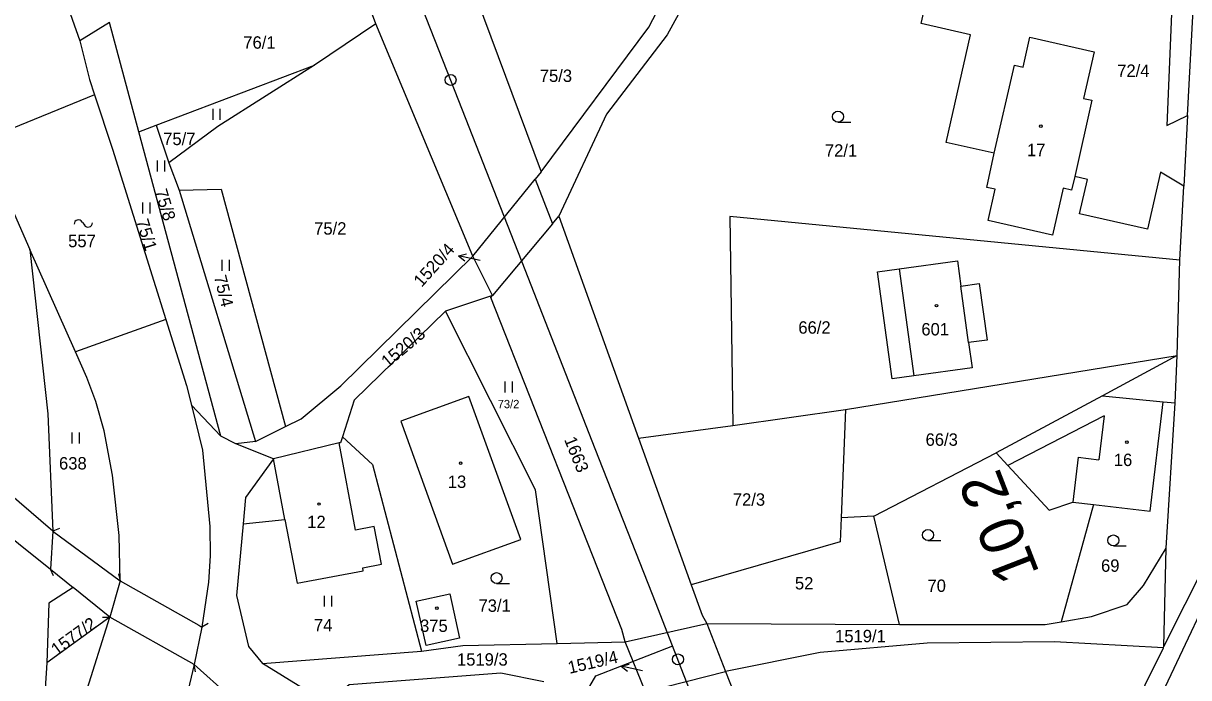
# Model space of a CAD drawing. Extents: x -553916 to -552953, y -1067470 to -1066637.
# Drawn here: x -553633.4 to -553473.7, y -1066907.8 to -1066818.1 of the extents above; entities that cross this region are included whole.
import ezdxf

# ---------------------------------------------------------------- set-up
doc = ezdxf.new("R2010")
doc.units = 0
for name, color, linetype in [('Hranice parcel', 7, 'Continuous'), ('Kolej', 7, 'Continuous'), ('Návěst místo trati', 7, 'Continuous'), ('Parcelní čísla', 7, 'Continuous'), ('Pop  PČ popisy', 7, 'Continuous'), ('Přejezd - štěrkové lože', 7, 'Continuous'), ('Vnitřní kresba', 7, 'Continuous'), ('Vrstva 1', 7, 'Continuous'), ('Značky budov', 7, 'Continuous'), ('Značky kultur', 7, 'Continuous')]:
    doc.layers.add(name, color=color, linetype=linetype)

msp = doc.modelspace()

# ---------------------------------------------------------------- linework, layer by layer
at = {"layer": 'Hranice parcel'}
for p, q in [((-553473.84, -1066830.72), (-553472.63, -1066808.29)), ((-553621.6, -1066817.99), (-553625.66, -1066820.5)), ((-553617.57, -1066832.95), (-553621.6, -1066817.99)), ((-553585.12, -1066818.17), (-553593.5, -1066823.84)), ((-553615.21, -1066832.06), (-553593.5, -1066823.84)), ((-553623.67, -1066827.87), (-553637.71, -1066833.62)), ((-553476.7, -1066832.08), (-553473.84, -1066830.72)), ((-553473.84, -1066830.72), (-553474.36, -1066840.41)), ((-553617.57, -1066832.95), (-553615.21, -1066832.06)), ((-553615.21, -1066832.06), (-553613.46, -1066837.22)), ((-553606.33, -1066874.71), (-553617.57, -1066832.95)), ((-553613.46, -1066837.22), (-553612.07, -1066840.94)), ((-553474.36, -1066840.41), (-553477.57, -1066838.5)), ((-553474.91, -1066850.54), (-553474.36, -1066840.41)), ((-553612.07, -1066840.94), (-553601.6, -1066875.43)), ((-553474.91, -1066850.54), (-553536.59, -1066844.58)), ((-553536.59, -1066844.58), (-553536.15, -1066873.24)), ((-553626.26, -1066863.15), (-553632.51, -1066849.1)), ((-553475.25, -1066863.65), (-553474.91, -1066850.54)), ((-553569.13, -1066855.4), (-553575.56, -1066857.54)), ((-553613.88, -1066858.68), (-553626.26, -1066863.15)), ((-553520.71, -1066871.05), (-553475.25, -1066863.65)), ((-553475.55, -1066870.13), (-553475.25, -1066863.65)), ((-553610.38, -1066870.43), (-553606.33, -1066874.71)), ((-553476.78, -1066890.04), (-553475.55, -1066870.13)), ((-553536.15, -1066873.24), (-553520.71, -1066871.05)), ((-553520.71, -1066871.05), (-553521.33, -1066885.91)), ((-553601.6, -1066875.43), (-553597.49, -1066873.38)), ((-553549.09, -1066874.96), (-553536.15, -1066873.24)), ((-553604.31, -1066875.73), (-553606.33, -1066874.71)), ((-553601.6, -1066875.43), (-553604.31, -1066875.73)), ((-553599.14, -1066877.81), (-553604.31, -1066875.73)), ((-553590.14, -1066875.63), (-553599.14, -1066877.81)), ((-553516.84, -1066885.65), (-553500.06, -1066876.99)), ((-553629.4, -1066887.71), (-553637.93, -1066880.39)), ((-553486.72, -1066884.07), (-553491.17, -1066900.15)), ((-553516.84, -1066885.65), (-553521.33, -1066885.91)), ((-553513.34, -1066900.54), (-553516.84, -1066885.65)), ((-553629.4, -1066887.71), (-553620.15, -1066894.52)), ((-553477.08, -1066903.52), (-553476.78, -1066890.04)), ((-553620.15, -1066894.52), (-553621.57, -1066899.49)), ((-553621.57, -1066899.49), (-553626.61, -1066895.43)), ((-553621.57, -1066899.49), (-553630.21, -1066905.76)), ((-553624.88, -1066910.1), (-553621.57, -1066899.49)), ((-553539.74, -1066900.36), (-553513.34, -1066900.54)), ((-553600.63, -1066905.86), (-553578.83, -1066904.19)), ((-553560.24, -1066903.11), (-553550.91, -1066902.91)), ((-553477.16, -1066903.7), (-553477.08, -1066903.52)), ((-553630.21, -1066905.76), (-553632.98, -1066948.88)), ((-553591.81, -1066911.32), (-553600.63, -1066905.86)), ((-553610.01, -1066906), (-553611.35, -1066911.57))]:
    msp.add_line(p, q, dxfattribs=at)
for points in [[(-553477.08, -1066903.52), (-553471.25, -1066891.92), (-553468.41, -1066870.82), (-553466.8, -1066842.82), (-553465.31, -1066811.26), (-553449.58, -1066745.18), (-553421.6, -1066636.65)], [(-553562.46, -1066838.44), (-553547.69, -1066818.62), (-553535.38, -1066795.04), (-553519.42, -1066775.8), (-553495.28, -1066749.85), (-553495.01, -1066748.81)], [(-553643.88, -1066774.03), (-553635.29, -1066793.34), (-553625.66, -1066820.5)], [(-553532.8, -1066797.02), (-553545.17, -1066819.67), (-553553.48, -1066830.52), (-553560.01, -1066844.54)], [(-553483.73, -1066809.15), (-553480.88, -1066809.9), (-553479.9, -1066810.22), (-553478.34, -1066811.42), (-553477.07, -1066812.9), (-553475.95, -1066814.54), (-553476.7, -1066832.08)], [(-553500.33, -1066835.91), (-553506.92, -1066834.42), (-553503.58, -1066819.65), (-553510.37, -1066818.12), (-553510, -1066816.53), (-553512.88, -1066815.92), (-553511.82, -1066810.98), (-553508.93, -1066811.58), (-553508.63, -1066810.19), (-553503.64, -1066811.31)], [(-553625.66, -1066820.5), (-553624.36, -1066825.78), (-553623.67, -1066827.87)], [(-553500.33, -1066835.91), (-553497.54, -1066823.83), (-553496.39, -1066824.1), (-553495.45, -1066820), (-553486.65, -1066822), (-553488.1, -1066828.38), (-553486.94, -1066828.63), (-553489.31, -1066839.1)], [(-553593.5, -1066823.84), (-553606.76, -1066832.22), (-553613.46, -1066837.22)], [(-553623.67, -1066827.87), (-553621.18, -1066835.35), (-553613.88, -1066858.68)], [(-553637.71, -1066833.62), (-553635.67, -1066841.32), (-553635.29, -1066842.84), (-553632.51, -1066849.1)], [(-553489.31, -1066839.1), (-553489.74, -1066840.96), (-553490.91, -1066840.7), (-553492.37, -1066847.14), (-553501.19, -1066845.13), (-553500.2, -1066840.84), (-553501.37, -1066840.59), (-553500.33, -1066835.91)], [(-553477.57, -1066838.5), (-553479.33, -1066846.32), (-553488.66, -1066844.2), (-553487.56, -1066839.48), (-553489.31, -1066839.1)], [(-553612.07, -1066840.94), (-553606.31, -1066840.83), (-553597.49, -1066873.38)], [(-553632.51, -1066849.1), (-553630.08, -1066871.62), (-553629.4, -1066887.71)], [(-553597.49, -1066873.38), (-553595.36, -1066872.31), (-553589.9, -1066867.8), (-553571.83, -1066850)], [(-553513.37, -1066851.75), (-553505.38, -1066850.65), (-553504.9, -1066854.14), (-553502.39, -1066853.78), (-553501.32, -1066861.52), (-553503.85, -1066861.86), (-553503.37, -1066865.34), (-553511.35, -1066866.43), (-553514.32, -1066866.85), (-553516.34, -1066852.16), (-553513.37, -1066851.75)], [(-553575.56, -1066857.54), (-553588.06, -1066869.75), (-553589.68, -1066874.77)], [(-553560.24, -1066903.11), (-553563.23, -1066882.03), (-553575.56, -1066857.54)], [(-553613.88, -1066858.68), (-553611.04, -1066867.75), (-553610.38, -1066870.43)], [(-553620.15, -1066894.52), (-553620.3, -1066888.33), (-553621.19, -1066880.03), (-553622.36, -1066873.98), (-553623.5, -1066869.95), (-553624.71, -1066866.63), (-553626.26, -1066863.15)], [(-553475.25, -1066863.65), (-553485.48, -1066869.15), (-553500.06, -1066876.99)], [(-553610.38, -1066870.43), (-553608.88, -1066876.59), (-553607.84, -1066887.1), (-553607.82, -1066891.09), (-553608.06, -1066894.72), (-553608.96, -1066900.89), (-553610.01, -1066906)], [(-553572.34, -1066869.25), (-553581.7, -1066872.64), (-553574.6, -1066892.26), (-553565.24, -1066888.87), (-553572.34, -1066869.25)], [(-553486.72, -1066884.07), (-553478.97, -1066884.99), (-553477.19, -1066869.97), (-553475.55, -1066870.13)], [(-553589.68, -1066874.77), (-553589.94, -1066875.59), (-553590.14, -1066875.63)], [(-553589.68, -1066874.77), (-553585.58, -1066878.58), (-553578.83, -1066904.19)], [(-553603.29, -1066886.71), (-553597.57, -1066886.1), (-553595.9, -1066894.86), (-553586.82, -1066893.14), (-553586.89, -1066892.75), (-553584.34, -1066892.26), (-553585.34, -1066887.07), (-553587.88, -1066887.56), (-553590.14, -1066875.63)], [(-553500.06, -1066876.99), (-553498.46, -1066878.73), (-553492.8, -1066884.85), (-553489.55, -1066883.74), (-553486.72, -1066884.07)], [(-553599.14, -1066877.81), (-553602.95, -1066883.09), (-553603.29, -1066886.71)], [(-553638.51, -1066885.89), (-553629.69, -1066892.95), (-553626.61, -1066895.43)], [(-553603.29, -1066886.71), (-553604.22, -1066896.53), (-553602.56, -1066903.53), (-553600.63, -1066905.86)], [(-553521.33, -1066885.91), (-553521.47, -1066889.2), (-553541.86, -1066895.1)], [(-553491.17, -1066900.15), (-553486.99, -1066899.43), (-553482.1, -1066897.78), (-553479.9, -1066895.18), (-553476.78, -1066890.04)], [(-553468.58, -1066891.47), (-553477.31, -1066909.92), (-553483.75, -1066931.3), (-553489.9, -1066939.2)], [(-553626.61, -1066895.43), (-553629.94, -1066897.59), (-553630.21, -1066905.76)], [(-553578.22, -1066903.39), (-553579.56, -1066897.34), (-553574.98, -1066896.32), (-553573.63, -1066902.38), (-553578.22, -1066903.39)], [(-553513.34, -1066900.54), (-553493.34, -1066900.53), (-553491.17, -1066900.15)], [(-553578.83, -1066904.19), (-553573.18, -1066903.38), (-553560.24, -1066903.11)], [(-553477.16, -1066903.7), (-553492.06, -1066902.9), (-553509.55, -1066903.09), (-553524.22, -1066904.36), (-553537.18, -1066906.98)], [(-553515.05, -1066965.6), (-553502.53, -1066951.2), (-553486.22, -1066930.56), (-553479.63, -1066908.8), (-553477.16, -1066903.7)], [(-553580.85, -1066983.77), (-553580.5, -1066981.61), (-553581.9, -1066962.72), (-553586.71, -1066945.98), (-553600.4, -1066914.59), (-553610.01, -1066906)], [(-553562.08, -1066908.37), (-553567.96, -1066907.21), (-553588.75, -1066908.8), (-553591.81, -1066911.32)]]:
    msp.add_lwpolyline(points, dxfattribs=at)
at = {"layer": 'Kolej'}
msp.add_lwpolyline([(-553503.32, -1067065.81), (-553502.68, -1067054.03), (-553502.76, -1067041.5), (-553503.63, -1067029.06), (-553504.76, -1067019.97), (-553506.18, -1067011.39), (-553508.33, -1067001.39), (-553510.95, -1066991.62), (-553512.92, -1066985.29), (-553515.65, -1066977.35), (-553517.42, -1066972.53), (-553519.16, -1066967.95), (-553522.89, -1066958.38), (-553529.1, -1066942.55), (-553538.69, -1066918.11), (-553542.91, -1066907.33), (-553546.69, -1066897.68), (-553555.03, -1066876.44), (-553564.64, -1066851.89), (-553574.24, -1066827.43), (-553583.19, -1066804.62)], dxfattribs=at)
at = {"layer": 'Návěst místo trati'}
for centre in [(-553574.86, -1066825.84), (-553543.69, -1066905.31)]:
    msp.add_circle(centre, 0.75, dxfattribs=at)
at = {"layer": 'Pop  PČ popisy'}
for p, q in [((-553573.76, -1066849.96), (-553572.67, -1066849.68)), ((-553570.82, -1066850.59), (-553573.76, -1066849.96)), ((-553573.76, -1066849.96), (-553572.89, -1066850.66)), ((-553551.46, -1066906.23), (-553550.37, -1066905.95)), ((-553548.53, -1066906.86), (-553551.46, -1066906.23)), ((-553551.46, -1066906.23), (-553550.59, -1066906.93))]:
    msp.add_line(p, q, dxfattribs=at)
at = {"layer": 'Přejezd - štěrkové lože'}
msp.add_lwpolyline([(-553598.54, -1066929.82), (-553559.03, -1066914.56), (-553554.95, -1066907.55), (-553544.41, -1066903.46)], dxfattribs=at)
at = {"layer": 'Vnitřní kresba'}
for p, q in [((-553513.37, -1066851.75), (-553511.35, -1066866.43)), ((-553503.85, -1066861.86), (-553504.9, -1066854.14)), ((-553485.48, -1066869.15), (-553477.19, -1066869.97)), ((-553485.28, -1066871.92), (-553498.46, -1066878.73)), ((-553485.28, -1066871.92), (-553485.99, -1066877.92)), ((-553597.57, -1066886.1), (-553599.14, -1066877.81)), ((-553488.82, -1066877.58), (-553489.55, -1066883.74)), ((-553488.82, -1066877.58), (-553485.99, -1066877.92)), ((-553629.4, -1066887.71), (-553629.69, -1066892.95)), ((-553628.47, -1066887.34), (-553629.4, -1066887.71)), ((-553629.27, -1066893.86), (-553629.69, -1066892.95)), ((-553620.39, -1066893.55), (-553620.15, -1066894.52)), ((-553620.15, -1066894.52), (-553609.37, -1066900.63)), ((-553622.57, -1066899.52), (-553621.57, -1066899.49)), ((-553610.01, -1066906), (-553621.57, -1066899.49)), ((-553609.37, -1066900.63), (-553608.96, -1066900.89)), ((-553608.1, -1066900.38), (-553608.96, -1066900.89)), ((-553609.84, -1066906.99), (-553610.01, -1066906))]:
    msp.add_line(p, q, dxfattribs=at)
at = {"layer": 'Vrstva 1'}
for p, q in [((-553573.62, -1066808.38), (-553562.46, -1066838.44)), ((-553571.83, -1066850), (-553585.12, -1066818.17)), ((-553562.46, -1066838.44), (-553563.28, -1066839.45)), ((-553571.83, -1066850), (-553563.28, -1066839.45)), ((-553563.28, -1066839.45), (-553560.9, -1066845.6)), ((-553560.9, -1066845.6), (-553560.01, -1066844.54)), ((-553560.01, -1066844.54), (-553549.09, -1066874.96)), ((-553560.9, -1066845.6), (-553569.13, -1066855.4)), ((-553569.13, -1066855.4), (-553571.83, -1066850)), ((-553549.09, -1066874.96), (-553541.86, -1066895.1)), ((-553550.91, -1066902.91), (-553539.74, -1066900.36)), ((-553539.74, -1066900.36), (-553537.18, -1066906.98)), ((-553548.13, -1066909.75), (-553550.91, -1066902.91)), ((-553548.13, -1066909.75), (-553537.18, -1066906.98))]:
    msp.add_line(p, q, dxfattribs=at)
for points in [[(-553585.12, -1066818.17), (-553585.42, -1066817.3), (-553592.22, -1066799.8)], [(-553550.91, -1066902.91), (-553551.37, -1066901.2), (-553569.36, -1066855.68), (-553569.13, -1066855.4)], [(-553541.86, -1066895.1), (-553540.37, -1066899.25), (-553539.74, -1066900.36)], [(-553537.18, -1066906.98), (-553519.04, -1066953.03), (-553515.05, -1066965.6)]]:
    msp.add_lwpolyline(points, dxfattribs=at)
at = {"layer": 'Značky budov'}
msp.add_line((-553625.36, -1066845.33), (-553625.06, -1066845.73), dxfattribs=at)
for centre in [(-553493.95, -1066832.18), (-553508.26, -1066856.8), (-553482.15, -1066875.51), (-553573.48, -1066878.39), (-553592.89, -1066884), (-553576.73, -1066898.27)]:
    msp.add_circle(centre, 0.175, dxfattribs=at)
for centre, start, end in [((-553625.87, -1066845.62), 29.2914, 181.2189), ((-553624.55, -1066845.44), 209.2914, 1.2189)]:
    msp.add_arc(centre, 0.588, start, end, dxfattribs=at)
at = {"layer": 'Značky kultur'}
for p, q in [((-553607.42, -1066831.3), (-553607.42, -1066829.8)), ((-553606.42, -1066831.3), (-553606.42, -1066829.8)), ((-553521.76, -1066831.63), (-553520.01, -1066831.63)), ((-553615.01, -1066838.4), (-553615.01, -1066836.9)), ((-553614.01, -1066838.4), (-553614.01, -1066836.9)), ((-553617.03, -1066844.16), (-553617.03, -1066842.66)), ((-553616.03, -1066844.16), (-553616.03, -1066842.66)), ((-553606.18, -1066852.02), (-553606.18, -1066850.52)), ((-553605.18, -1066852.02), (-553605.18, -1066850.52)), ((-553567.36, -1066868.69), (-553567.36, -1066867.19)), ((-553566.36, -1066868.69), (-553566.36, -1066867.19)), ((-553626.71, -1066875.71), (-553626.71, -1066874.21)), ((-553625.71, -1066875.71), (-553625.71, -1066874.21)), ((-553509.42, -1066888.99), (-553507.67, -1066888.99)), ((-553484.01, -1066889.74), (-553482.26, -1066889.74)), ((-553568.55, -1066894.9), (-553566.8, -1066894.9)), ((-553592.13, -1066898.07), (-553592.13, -1066896.57)), ((-553591.13, -1066898.07), (-553591.13, -1066896.57))]:
    msp.add_line(p, q, dxfattribs=at)
for centre in [(-553521.76, -1066830.88), (-553509.42, -1066888.24), (-553484.01, -1066888.99), (-553568.55, -1066894.15)]:
    msp.add_circle(centre, 0.75, dxfattribs=at)

# ---------------------------------------------------------------- texts
at = {"layer": 'Návěst místo trati'}
msp.add_text('10,2', height=6, rotation=111.2039, dxfattribs=at).set_placement((-553494.09, -1066893.45))
at = {"layer": 'Parcelní čísla'}
for s, height, p in [('76/1', 1.7, (-553603.27, -1066821.56)), ('75/3', 1.7, (-553562.63, -1066826.12)), ('72/4', 1.7, (-553483.48, -1066825.43)), ('75/7', 1.7, (-553614.25, -1066834.78)), ('72/1', 1.7, (-553523.55, -1066836.37)), ('17', 1.7, (-553495.86, -1066836.3)), ('75/2', 1.7, (-553593.56, -1066847.06)), ('557', 1.7, (-553627.28, -1066848.78)), ('66/2', 1.7, (-553527.19, -1066860.64)), ('601', 1.7, (-553510.33, -1066860.88)), ('73/2', 1.14, (-553568.4, -1066870.86)), ('66/3', 1.7, (-553509.75, -1066876.01)), ('16', 1.7, (-553483.95, -1066878.79)), ('638', 1.7, (-553628.53, -1066879.26)), ('13', 1.7, (-553575.24, -1066881.79)), ('72/3', 1.7, (-553536.17, -1066884.23)), ('12', 1.7, (-553594.51, -1066887.3)), ('69', 1.7, (-553485.7, -1066893.29)), ('52', 1.7, (-553527.66, -1066895.71)), ('70', 1.7, (-553509.49, -1066896.05)), ('73/1', 1.7, (-553571.03, -1066898.78)), ('74', 1.7, (-553593.59, -1066901.46)), ('375', 1.7, (-553579.04, -1066901.54)), ('1519/1', 1.7, (-553522.15, -1066902.95)), ('1519/3', 1.7, (-553573.98, -1066906.16))]:
    msp.add_text(s, height=height, dxfattribs=at).set_placement(p)
for s, rotation, p in [('75/8', 287, (-553615.42, -1066841.09)), ('75/1', 287, (-553617.97, -1066845.2)), ('75/4', 284, (-553607.31, -1066852.83)), ('1520/3', 40, (-553583.48, -1066865.39)), ('1577/2', 36, (-553628.84, -1066904.86))]:
    msp.add_text(s, height=1.7, rotation=rotation, dxfattribs=at).set_placement(p)
at = {"layer": 'Vrstva 1'}
for s, rotation, p in [('1520/4', 48, (-553578.83, -1066854.36)), ('1663', 292, (-553559.32, -1066875.16)), ('1519/4', 13, (-553558.56, -1066907.29))]:
    msp.add_text(s, height=1.7, rotation=rotation, dxfattribs=at).set_placement(p)

doc.saveas('drawing.dxf')
